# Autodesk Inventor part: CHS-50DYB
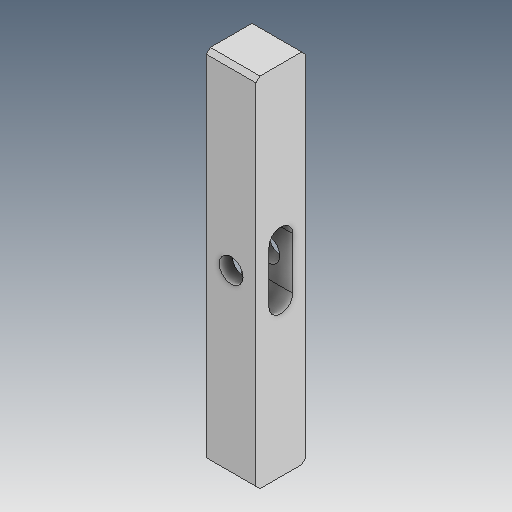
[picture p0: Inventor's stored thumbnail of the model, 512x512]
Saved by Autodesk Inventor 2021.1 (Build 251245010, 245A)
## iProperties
Created: 2019-04
Part Number: CHS-50DYB
Material: Ogólny
Document SubType Name: Modeling
Designer: user
Density: 1 g/cm^3
Appearance: Domyślna
Author: user
Revision Number: ÈÎºÎ
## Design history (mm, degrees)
feature "ÊäÈë1"
node "Bryła1"
